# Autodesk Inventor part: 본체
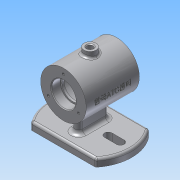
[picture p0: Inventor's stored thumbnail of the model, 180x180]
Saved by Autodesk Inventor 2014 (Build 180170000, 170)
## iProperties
Created: 2017-12
Part Number: 본체
Material: 알루미늄 6061
Document SubType Name: Modeling
Designer: user
Density: 2.71 g/cm^3
Appearance: 알루미늄 - 평지
Mass: 467.692 g
Surface Area: 486.484 cm^2
Volume: 172.58 cm^3
Author: user
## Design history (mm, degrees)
sketch "스케치1"
  geometry: C1 r 30 at (0, 0); 1 further point
  constraints: 1 centre point, 1 coincident
  dimensions: "d0" = 60 diameter of C1
extrude "돌출1" new body sketch "스케치1" stored distance "d1" = 70; taper "d2" = 0 deg
sketch "스케치2"
  geometry: C1 r 30 at (0, 0) reference; 3 further points
  constraints: 1 vertical alignment, 4 other
  dimensions: "d3" = 23 distance of point (0, 23) C1.centre; "d6" = 360 deg dimension on C1.centre point (0, 23) (derived)
hole "구멍1" sketch "스케치2" at (0, 23), (-19.919, -11.5), (19.919, -11.5) diameter "d8" = 3.242; stored, may be unused: countersink angle "d12" = 90 deg, drill point angle "d14" = 118 deg; dims "d9" = 8, "d10" = 4, "d11" = 2, "d13" = 10
sketch "스케치3"
  geometry: C1 r 30 at (0, 0) reference; C2 r 16 at (0, 0)
  constraints: 1 centre point, 1 coincident
  dimensions: "d15" = 32 diameter of C2
extrude "돌출2" cut sketch "스케치3" distance "d16" = 12; taper "d17" = 0 deg
sketch "스케치4"
  geometry: C1 r 16 at (0, 0) reference; C2 r 14 at (0, 0)
  constraints: 1 centre point, 1 coincident
  dimensions: "d18" = 28 diameter of C2
extrude "돌출3" cut sketch "스케치4" distance "d19" = 3; taper "d20" = 0 deg
fillet "모깎기1" dims "d21" = 0.3
sketch "스케치5"
  geometry: C1 r 14 at (0, 0) reference; C2 r 25 at (0, 0)
  constraints: 1 centre point, 1 coincident
  dimensions: "d22" = 50 diameter of C2
extrude "돌출4" cut sketch "스케치5" distance "d23" = 40; taper "d24" = 0 deg
chamfer "모따기1" distance "d25" = 1; stored, may be unused: second distance "d26" = 2, angle "d27" = 45 deg
node "작업 평면1"
sketch "스케치6"
  geometry: L1 (42.426, 35)-(-42.426, 35); L2 (42.426, -35)-(-42.426, -35); A1 r 55 centre (0, 0) between (42.426, 35) and (-42.426, 35); 1 further point
  constraints: 4 end point, 4 point on circle, 1 centre point, 1 coincident, 1 horizontal, 1 parallel
  dimensions: "d29" = 110 diameter of A1; "d30" = 35 distance from line of L1 A1.centre; "d31" = 70 distance between parallel lines of L2 L1
extrude "돌출5" join sketch "스케치6" distance "d32" = 10; taper "d33" = 0 deg
sketch "스케치7"
  geometry: L1 (42.426, 35)-(-42.426, 35) reference; L2 (0, -15)-(0, 15); L3 (-5, -15)-(-5, 15); L4 (5, 15)-(5, -15); A1 r 55 centre (0, 0) between (-42.426, 35) and (-42.426, -35) reference; A2 r 5 centre (0, -15) between (-5, -15) and (5, -15); A3 r 5 centre (0, 15) between (5, 15) and (-5, 15)
  constraints: 8 end point, 4 point on circle, 4 tangent, 2 centre point, 1 midpoint, 1 parallel, 1 perpendicular
  dimensions: "d34" = 30 distance of L2.end L2.start; "d35" = 5 radius of A2
extrude "돌출6" join sketch "스케치7" stored distance "d36" = 10; taper "d37" = 0 deg
fillet "모깎기2" dims "d38" = 5
sketch "스케치8"
  geometry: L1 (-42.426, -35)-(42.426, -35) reference; L2 (-40, 0)-(-24, 0); L3 (-40, -5)-(-24, -5); L4 (-24, 5)-(-40, 5); A1 r 55 centre (0, 0) between (42.426, -35) and (42.426, 35) reference; A2 r 10 centre (0, -15) between (-10, -15) and (10, -15) reference; A3 r 5 centre (-40, 0) between (-40, 5) and (-40, -5); A4 r 5 centre (-24, 0) between (-24, -5) and (-24, 5); 1 further point
  constraints: 8 end point, 4 point on circle, 4 tangent, 2 centre point, 2 parallel, 1 horizontal alignment, 1 midpoint
  dimensions: "d39" = 16 distance of L2.end L2.start; "d40" = 24 horizontal distance of A2.centre L2.end; "d41" = 5 radius of A3
extrude "돌출7" cut sketch "스케치8" distance "d42" = 10; taper "d43" = 0 deg
fillet "모깎기3" dims "d44" = 3
fillet "모깎기4" dims "d45" = 3
fillet "모깎기5" dims "d46" = 3
node "작업 평면2"
sketch "스케치9"
  geometry: C1 r 8 at (0, 0); 1 further point
  constraints: 1 centre point, 1 coincident
  dimensions: "d48" = 16 diameter of C1
extrude "돌출8" join sketch "스케치9" stored distance "d49" = 10; taper "d50" = 0 deg
sketch "스케치10"
  geometry: C1 r 8 at (0, 0) reference; C2 r 4 at (0, 0)
  constraints: 1 centre point, 1 coincident
  dimensions: "d51" = 8 diameter of C2
extrude "돌출9" cut sketch "스케치10" distance "d52" = 20; taper "d53" = 0 deg
chamfer "모따기2" distance "d54" = 1; stored, may be unused: second distance "d55" = 2, angle "d56" = 45 deg
node "작업 평면3"
sketch "스케치11"
  geometry: L1 (30, 35)-(-30, 35) reference; 2 further points
  constraints: 1 other
  dimensions: "d57" = 35 distance from line of L1 point (0, 0); "d58" = 30 horizontal distance of L1.start point (0, 0)
feature "엠보싱1" sketch "스케치11" dims "d2" = 0, "d59" = 0.5, "d60" = 0
fillet "모깎기6" dims "d61" = 3
node "솔리드1"
mirror "대칭1"
mirror "대칭2"
mirror "대칭3"
other parameters: "d28" = -62, "d47" = 37
